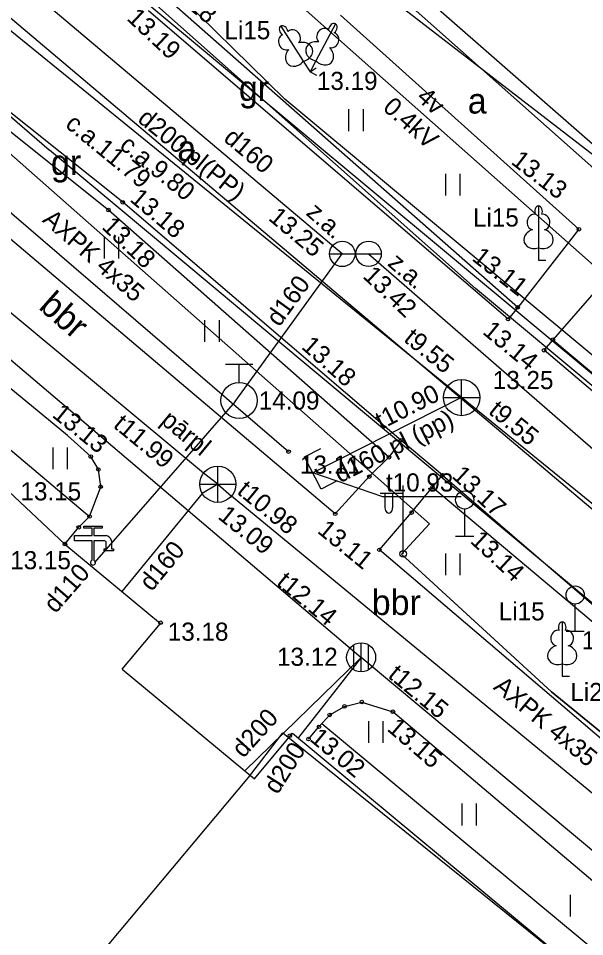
# Model space of a CAD drawing. Extents: x 503877 to 504025, y 304562 to 304725.
# Drawn here: x 503933 to 503948.61, y 304593.32 to 304618.66 of the extents above; entities that cross this region are included whole.
import ezdxf

# ---------------------------------------------------------------- set-up
doc = ezdxf.new("R2010")
doc.units = 0
for name, color, linetype in [('24', 7, 'Continuous'), ('25', 7, 'Continuous'), ('42', 7, 'Continuous'), ('APGS_ACRL_####_####_#', 7, 'Continuous'), ('APGS_ELEM_####_####_#', 7, 'Continuous'), ('APGS_VADP_ZSPR_####_#', 7, 'Continuous'), ('APGS_VADP_ZSPR_TKST_#', 7, 'Continuous'), ('BUVE_BDET_####_####_#', 7, 'Continuous'), ('BUVE_EKAS_####_####_#', 7, 'Continuous'), ('CELI_CMAL_####_####_#', 7, 'Continuous'), ('CELI_CSEG_####_TKST_#', 7, 'Continuous'), ('CELI_ELEM_####_####_#', 7, 'Continuous'), ('CELI_TAKA_####_####_#', 7, 'Continuous'), ('ELEK_VADV_ZSPR_####_#', 7, 'Continuous'), ('ELEK_VADV_ZSPR_TKST_#', 7, 'Continuous'), ('GAZE_VADP_VSP2_####_#', 7, 'Continuous'), ('Level 46', 7, 'Continuous'), ('LKAN_ELEM_####_####_#', 7, 'Continuous'), ('LKAN_ELEM_PAST_TKST_#', 7, 'Continuous'), ('LKAN_VADP_PAST_####_#', 7, 'Continuous'), ('LKAN_VADP_PAST_TKST_#', 7, 'Continuous'), ('RELJ_AATZ_####_TKST_#', 7, 'Continuous'), ('RELJ_ELEM_####_####_#', 7, 'Continuous'), ('SAKK_KKAN_####_####_#', 7, 'Continuous'), ('SAKT_VADP_KABE_####_#', 7, 'Continuous'), ('SAKT_VADP_NEDR_####_#', 7, 'Continuous'), ('SKAN_ELEM_####_####_#', 7, 'Continuous'), ('SKAN_ELEM_PAST_TKST_#', 7, 'Continuous'), ('SKAN_VADP_PAST_####_#', 7, 'Continuous'), ('SKAN_VADP_PAST_####_I', 7, 'Continuous'), ('SKAN_VADP_PAST_TKST_#', 7, 'Continuous'), ('SKAN_VADP_PAST_TKST_I', 7, 'Continuous'), ('SKAN_VADP_SPDK_TKST_I', 7, 'Continuous'), ('TERT_DIAM_####_TKST_#', 7, 'Continuous'), ('TERT_ELEM_####_####_#', 7, 'Continuous'), ('TERT_KRND_####_####_#', 7, 'Continuous'), ('UDTK_ELEM_####_####_#', 7, 'Continuous'), ('UDTK_ELEM_####_TKST_#', 7, 'Continuous'), ('UDTK_VADP_UDEN_####_#', 7, 'Continuous'), ('UDTK_VADP_UDEN_####_I', 7, 'Continuous'), ('UDTK_VADP_UDEN_TKST_#', 7, 'Continuous')]:
    doc.layers.add(name, color=color, linetype=linetype)

msp = doc.modelspace()

# ---------------------------------------------------------------- linework, layer by layer
at = {"layer": '24'}
msp.add_line((503960.823, 304605.633), (503933.144, 304627.024), dxfattribs=at)
at = {"layer": '25'}
msp.add_line((503924.947, 304625.297), (503985.325, 304574.255), dxfattribs=at)
at = {"layer": '42'}
msp.add_lwpolyline([(503940.294, 304598.947), (503951.661, 304589.773), (503949.864, 304587.645), (503954.733, 304583.621), (503953.927, 304582.557), (503960.49, 304577.208), (503958.987, 304575.41), (503959.865, 304574.697), (503955.838, 304569.828), (503955.063, 304570.502), (503953.67, 304568.891), (503946.74, 304574.542), (503947.217, 304575.092), (503942.561, 304578.835), (503942.084, 304578.358), (503930.754, 304587.457), (503939.344, 304597.708)], close=True, dxfattribs=at)
at = {"layer": 'APGS_ACRL_####_####_#'}
for p, q in [((503947.7, 304600.079), (503944.899, 304602.648)), ((503955.54, 304593.612), (503947.7, 304600.079))]:
    msp.add_line(p, q, dxfattribs=at)
at = {"layer": 'APGS_ELEM_####_####_#'}
for p, q in [((503943.611, 304603.885), (503943.611, 304605.768)), ((503943.611, 304605.552), (503942.976, 304605.547)), ((503943.111, 304605.548), (503943.111, 304605.156)), ((503943.321, 304605.55), (503943.321, 304605.156))]:
    msp.add_line(p, q, dxfattribs=at)
msp.add_circle((503943.611, 304603.885), 0.09, dxfattribs=at)
msp.add_ellipse((503943.216, 304605.156), major_axis=(0, 0.151), ratio=0.695971, start_param=1.570796, end_param=4.712389, dxfattribs=at)
at = {"layer": 'APGS_VADP_ZSPR_####_#'}
for p, q in [((503930.322, 304617.086), (503944.336, 304604.708)), ((503944.336, 304604.708), (503943.564, 304603.872)), ((503943.564, 304603.872), (503947.7, 304600.079)), ((503947.7, 304600.079), (503955.752, 304593.437))]:
    msp.add_line(p, q, dxfattribs=at)
at = {"layer": 'BUVE_BDET_####_####_#'}
msp.add_line((503941.373, 304599.205), (503951.794, 304590.537), dxfattribs=at)
at = {"layer": 'BUVE_EKAS_####_####_#'}
for p, q in [((503927.634, 304610.394), (503934.287, 304604.153)), ((503934.287, 304604.153), (503936.919, 304601.964)), ((503935.866, 304600.697), (503936.919, 304601.964)), ((503935.866, 304600.697), (503939.51, 304597.678)), ((503939.51, 304597.678), (503940.557, 304598.938)), ((503940.557, 304598.938), (503951.781, 304589.603))]:
    msp.add_line(p, q, dxfattribs=at)
at = {"layer": 'CELI_CMAL_####_####_#'}
for p, q in [((503950.55, 304613.018), (503942.522, 304620.157)), ((503946.502, 304610.359), (503936.593, 304618.863)), ((503941.882, 304618.748), (503948.456, 304612.839)), ((503935.883, 304613.584), (503931.107, 304617.397)), ((503941.74, 304604.987), (503929.195, 304615.6)), ((503943.556, 304607.012), (503935.883, 304613.584)), ((503947.498, 304609.501), (503950.55, 304613.018)), ((503948.456, 304612.839), (503946.769, 304610.685)), ((503927.574, 304611.135), (503934.968, 304604.913)), ((503934.355, 304607.151), (503929.569, 304611.095)), ((503946.769, 304610.685), (503946.502, 304610.359)), ((503962.594, 304596.657), (503947.498, 304609.501)), ((503935, 304606.567), (503934.355, 304607.151)), ((503943.556, 304607.012), (503943.218, 304606.546)), ((503944.692, 304606.054), (503943.556, 304607.012)), ((503935.209, 304606.21), (503935, 304606.567)), ((503943.218, 304606.546), (503942.679, 304606.013)), ((503935.274, 304605.736), (503935.209, 304606.21)), ((503942.679, 304606.013), (503941.74, 304604.987)), ((503944.42, 304605.72), (503944.692, 304606.054)), ((503944.692, 304606.054), (503957.877, 304594.69)), ((503934.968, 304604.913), (503935.274, 304605.736)), ((503943.846, 304605.021), (503944.42, 304605.72)), ((503934.67, 304604.614), (503934.968, 304604.913)), ((503942.956, 304603.993), (503943.846, 304605.021)), ((503934.287, 304604.153), (503934.67, 304604.614)), ((503956.326, 304592.583), (503942.956, 304603.993)), ((503941.995, 304599.672), (503942.472, 304599.793)), ((503942.472, 304599.793), (503943.33, 304599.524)), ((503941.587, 304599.439), (503941.995, 304599.672)), ((503954.372, 304590.15), (503943.33, 304599.524)), ((503941.291, 304599.109), (503941.587, 304599.439)), ((503941.005, 304598.769), (503941.291, 304599.109))]:
    msp.add_line(p, q, dxfattribs=at)
at = {"layer": 'CELI_ELEM_####_####_#'}
for p, q in [((503945.309, 304604.369), (503945.309, 304605.119)), ((503945.059, 304604.369), (503945.559, 304604.369)), ((503948.353, 304601.746), (503948.353, 304602.496)), ((503948.103, 304601.746), (503948.603, 304601.746))]:
    msp.add_line(p, q, dxfattribs=at)
for centre in [(503945.309, 304605.369), (503948.353, 304602.746)]:
    msp.add_circle(centre, 0.25, dxfattribs=at)
at = {"layer": 'CELI_TAKA_####_####_#'}
for p, q in [((503946.769, 304610.685), (503936.798, 304619.482)), ((503935.489, 304613.368), (503931.027, 304616.929)), ((503943.218, 304606.546), (503935.489, 304613.368)), ((503947.74, 304609.79), (503962.913, 304596.977)), ((503944.42, 304605.72), (503957.828, 304594.446))]:
    msp.add_line(p, q, dxfattribs=at)
at = {"layer": 'ELEK_VADV_ZSPR_####_#'}
msp.add_line((503938.2, 304621.309), (503972.501, 304590.85), dxfattribs=at)
at = {"layer": 'GAZE_VADP_VSP2_####_#'}
for p, q in [((503928.77, 304619.428), (503933.852, 304615.028)), ((503933.862, 304615.034), (503938.375, 304611.261)), ((503938.375, 304611.261), (503939.829, 304610.045)), ((503939.829, 304610.045), (503957.313, 304595.425))]:
    msp.add_line(p, q, dxfattribs=at)
at = {"layer": 'Level 46'}
msp.add_line((503943.333, 304620.019), (504006.701, 304564.361), dxfattribs=at)
at = {"layer": 'LKAN_ELEM_####_####_#'}
for p, q in [((503942.253, 304600.68), (503942.253, 304601.372)), ((503942.453, 304600.626), (503942.453, 304601.426)), ((503942.653, 304600.68), (503942.653, 304601.372))]:
    msp.add_line(p, q, dxfattribs=at)
msp.add_circle((503942.453, 304601.026), 0.4, dxfattribs=at)
at = {"layer": 'LKAN_VADP_PAST_####_#'}
for p, q in [((503924.482, 304616.293), (503942.453, 304601.026)), ((503939.243, 304597.899), (503942.453, 304601.026)), ((503942.453, 304601.026), (503940.729, 304598.812)), ((503953.386, 304591.874), (503942.453, 304601.026))]:
    msp.add_line(p, q, dxfattribs=at)
at = {"layer": 'RELJ_ELEM_####_####_#'}
for centre in [(503935.883, 304613.584), (503935.489, 304613.368), (503948.456, 304612.839), (503946.769, 304610.685), (503946.502, 304610.359), (503947.74, 304609.79), (503947.498, 304609.501), (503943.556, 304607.012), (503935, 304606.567), (503940.453, 304606.703), (503943.218, 304606.546), (503935.209, 304606.21), (503942.679, 304606.013), (503944.692, 304606.054), (503935.274, 304605.736), (503944.42, 304605.72), (503934.968, 304604.913), (503941.74, 304604.987), (503943.846, 304605.021), (503934.67, 304604.614), (503934.287, 304604.153), (503942.956, 304603.993), (503936.927, 304601.982), (503942.472, 304599.793), (503941.995, 304599.672), (503943.33, 304599.524), (503941.587, 304599.439), (503941.291, 304599.109), (503940.487, 304598.862), (503941.005, 304598.769)]:
    msp.add_circle(centre, 0.05, dxfattribs=at)
at = {"layer": 'SAKK_KKAN_####_####_#'}
for p, q in [((503945.607, 304611.208), (503936.176, 304619.589)), ((503968.613, 304591.954), (503945.607, 304611.208))]:
    msp.add_line(p, q, dxfattribs=at)
at = {"layer": 'SAKT_VADP_KABE_####_#'}
for p, q in [((503940.354, 304616.433), (503936.38, 304620.327)), ((503971.653, 304590.306), (503940.354, 304616.433))]:
    msp.add_line(p, q, dxfattribs=at)
at = {"layer": 'SAKT_VADP_NEDR_####_#'}
msp.add_line((503997.217, 304568.475), (503924.507, 304629.123), dxfattribs=at)
at = {"layer": 'SKAN_ELEM_####_####_#'}
for p, q in [((503945.224, 304607.695), (503945.224, 304608.695)), ((503944.724, 304608.195), (503945.724, 304608.195)), ((503938.502, 304605.302), (503938.502, 304606.302)), ((503938.002, 304605.802), (503939.002, 304605.802))]:
    msp.add_line(p, q, dxfattribs=at)
msp.add_lwpolyline([(503941.794, 304605.895), (503941.348, 304605.669), (503940.896, 304606.561), (503941.342, 304606.787)], dxfattribs=at)
for centre in [(503945.224, 304608.195), (503938.502, 304605.802)]:
    msp.add_circle(centre, 0.5, dxfattribs=at)
at = {"layer": 'SKAN_VADP_PAST_####_#'}
for p, q in [((503938.11, 304606.113), (503924.52, 304617.411)), ((503938.502, 304605.802), (503938.11, 304606.113)), ((503938.502, 304605.802), (503938.072, 304605.546)), ((503938.502, 304605.802), (503938.881, 304605.476)), ((503938.072, 304605.546), (503935.86, 304602.845)), ((503971.339, 304578.696), (503938.881, 304605.476))]:
    msp.add_line(p, q, dxfattribs=at)
at = {"layer": 'SKAN_VADP_PAST_####_I'}
for p, q in [((503945.224, 304608.195), (503926.692, 304623.27)), ((503945.224, 304608.195), (503941.122, 304606.115)), ((503973.287, 304585.319), (503945.224, 304608.195))]:
    msp.add_line(p, q, dxfattribs=at)
at = {"layer": 'SKAN_VADP_PAST_TKST_I'}
msp.add_lwpolyline([(503945.214, 304605.453), (503943.055, 304605.453), (503941.122, 304606.115)], dxfattribs=at)
at = {"layer": 'TERT_ELEM_####_####_#'}
for p, q in [((503940.859, 304617.476), (503941.047, 304617.184)), ((503941.208, 304617.491), (503941.047, 304617.184)), ((503941.047, 304617.184), (503941.215, 304617.292)), ((503941.047, 304617.184), (503941.224, 304617.091)), ((503942.117, 304615.551), (503942.117, 304616.151)), ((503942.517, 304615.551), (503942.517, 304616.151)), ((503944.786, 304613.77), (503944.786, 304614.37)), ((503945.186, 304613.77), (503945.186, 304614.37)), ((503935.374, 304612.034), (503935.374, 304612.634)), ((503935.774, 304612.034), (503935.774, 304612.634)), ((503947.343, 304612.331), (503947.343, 304611.984)), ((503947.343, 304611.984), (503947.543, 304611.984)), ((503938.148, 304609.73), (503938.148, 304610.33)), ((503938.548, 304609.73), (503938.548, 304610.33)), ((503933.962, 304606.221), (503933.962, 304606.821)), ((503934.362, 304606.221), (503934.362, 304606.821)), ((503944.786, 304603.296), (503944.786, 304603.896)), ((503945.186, 304603.296), (503945.186, 304603.896)), ((503947.997, 304600.851), (503947.997, 304600.504)), ((503947.997, 304600.504), (503948.197, 304600.504)), ((503942.663, 304598.664), (503942.663, 304599.264)), ((503943.063, 304598.664), (503943.063, 304599.264)), ((503945.234, 304596.39), (503945.234, 304596.99)), ((503945.634, 304596.39), (503945.634, 304596.99)), ((503948.225, 304593.876), (503948.225, 304594.476))]:
    msp.add_line(p, q, dxfattribs=at)
for points in [[(503940.235, 304618.445), (503940.859, 304617.476)], [(503940.436, 304618.298), (503940.435, 304618.299)], [(503941.745, 304618.512), (503941.208, 304617.491)], [(503941.716, 304618.264), (503941.715, 304618.266)], [(503947.343, 304613.484), (503947.343, 304612.331)], [(503947.433, 304613.252), (503947.432, 304613.253)], [(503947.997, 304602.004), (503947.997, 304600.851)], [(503948.087, 304601.772), (503948.086, 304601.773)]]:
    msp.add_lwpolyline(points, dxfattribs=at)
for centre, major_axis, ratio, start_param, end_param in [((503941.675, 304618.379), (-0.07, -0.133), 0.707107, 3.14537, 5.287485), ((503940.317, 304618.319), (0.081, -0.126), 0.707107, 3.14537, 5.287485), ((503940.316, 304618.319), (0.081, -0.126), 0.707107, 0.995701, 3.137816), ((503940.584, 304618.141), (0.148, -0.158), 0.861323, 0, 3.141593), ((503941.424, 304618.178), (-0.133, -0.17), 0.861323, 3.141593, 6.283185), ((503941.675, 304618.379), (-0.07, -0.133), 0.707107, 0.995701, 3.137816), ((503940.368, 304618.002), (0.082, -0.2), 0.861323, 3.141593, 6.283185), ((503941.243, 304617.751), (0.316, -0.059), 0.814445, 1.570796, 4.752015), ((503941.651, 304618.058), (-0.065, -0.206), 0.861323, 0, 3.141593), ((503940.651, 304617.634), (0.206, 0.246), 0.814445, 1.570796, 4.752015), ((503940.801, 304617.731), (-0.309, -0.086), 0.814445, 1.531171, 4.712389), ((503941.402, 304617.667), (-0.227, 0.227), 0.814445, 1.531171, 4.712389), ((503947.343, 304613.334), (0, -0.15), 0.707107, 3.14537, 5.287485), ((503947.343, 304613.334), (0, -0.15), 0.707107, 0.995701, 3.137816), ((503947.215, 304613.039), (-0.039, -0.212), 0.861323, 3.141593, 6.283185), ((503947.471, 304613.039), (0.039, -0.212), 0.861323, 0, 3.141593), ((503947.253, 304612.577), (0.307, 0.095), 0.814445, 1.570796, 4.752015), ((503947.433, 304612.577), (-0.307, 0.095), 0.814445, 1.531171, 4.712389), ((503947.997, 304601.854), (0, -0.15), 0.707107, 3.14537, 5.287485), ((503947.997, 304601.854), (0, -0.15), 0.707107, 0.995701, 3.137816), ((503947.869, 304601.559), (-0.039, -0.212), 0.861323, 3.141593, 6.283185), ((503948.125, 304601.559), (0.039, -0.212), 0.861323, 0, 3.141593), ((503947.907, 304601.097), (0.307, 0.095), 0.814445, 1.570796, 4.752015), ((503948.087, 304601.097), (-0.307, 0.095), 0.814445, 1.531171, 4.712389)]:
    msp.add_ellipse(centre, major_axis=major_axis, ratio=ratio, start_param=start_param, end_param=end_param, dxfattribs=at)
at = {"layer": 'TERT_KRND_####_####_#'}
msp.add_line((503929.802, 304615.876), (503940.453, 304606.703), dxfattribs=at)
at = {"layer": 'UDTK_ELEM_####_####_#'}
for p, q in [((503941.582, 304612.16), (503942.284, 304612.16)), ((503942.307, 304612.162), (503943.009, 304612.162)), ((503938.714, 304609.114), (503939.464, 304609.114)), ((503939.089, 304608.614), (503939.089, 304609.114)), ((503934.811, 304604.592), (503934.811, 304604.642)), ((503934.811, 304604.642), (503935.311, 304604.642)), ((503935.036, 304604.592), (503934.811, 304604.592)), ((503935.036, 304604.392), (503935.036, 304604.592)), ((503935.311, 304604.592), (503935.086, 304604.592)), ((503935.086, 304604.592), (503935.086, 304604.392)), ((503935.311, 304604.642), (503935.311, 304604.592)), ((503934.55, 304604.392), (503935.036, 304604.392)), ((503934.55, 304604.242), (503934.55, 304604.392)), ((503935.086, 304604.392), (503935.422, 304604.392)), ((503935.036, 304604.242), (503934.55, 304604.242)), ((503935.036, 304603.706), (503935.036, 304604.242)), ((503935.392, 304604.242), (503935.086, 304604.242)), ((503935.086, 304604.242), (503935.086, 304603.706)), ((503935.422, 304604.018), (503935.422, 304604.213)), ((503935.572, 304604.242), (503935.572, 304604.018)), ((503935.372, 304603.968), (503935.372, 304604.018)), ((503935.372, 304604.018), (503935.422, 304604.018)), ((503935.622, 304603.968), (503935.372, 304603.968)), ((503935.572, 304604.018), (503935.622, 304604.018)), ((503935.622, 304604.018), (503935.622, 304603.968))]:
    msp.add_line(p, q, dxfattribs=at)
for centre, radius in [((503941.933, 304612.16), 0.351), ((503942.658, 304612.162), 0.351), ((503939.089, 304608.114), 0.5)]:
    msp.add_circle(centre, radius, dxfattribs=at)
for centre, radius, start, end in [((503935.353, 304604.174), 0.229, 17.4344, 72.5656), ((503935.353, 304604.174), 0.0792, 29.8818, 60.1182), ((503935.061, 304603.642), 0.069, 111.235, 68.765)]:
    msp.add_arc(centre, radius, start, end, dxfattribs=at)
at = {"layer": 'UDTK_VADP_UDEN_####_#'}
for p, q in [((503941.933, 304612.16), (503932.733, 304619.928)), ((503938.985, 304608.09), (503941.933, 304612.16)), ((503938.985, 304608.09), (503935.103, 304603.648))]:
    msp.add_line(p, q, dxfattribs=at)
at = {"layer": 'UDTK_VADP_UDEN_####_I'}
for p, q in [((503941.933, 304612.16), (503942.658, 304612.162)), ((503942.658, 304612.162), (503968.511, 304589.634))]:
    msp.add_line(p, q, dxfattribs=at)

# ---------------------------------------------------------------- texts
at = {"layer": 'APGS_VADP_ZSPR_TKST_#'}
for rotation, p in [(318.5463, (503933.64, 304613.062)), (320.1197, (503946.074, 304600.168))]:
    msp.add_text('AXPK 4x35', height=0.5, rotation=rotation, dxfattribs=at).set_placement(p)
at = {"layer": 'CELI_CSEG_####_TKST_#'}
for s, p in [('gr', (503939.083, 304616.379)), ('a', (503945.392, 304616.033)), ('a', (503937.386, 304614.724)), ('gr', (503933.903, 304614.336)), ('bbr', (503942.746, 304602.195))]:
    msp.add_text(s, height=0.7, dxfattribs=at).set_placement(p)
msp.add_text('bbr', height=0.7, rotation=318.6552, dxfattribs=at).set_placement((503933.534, 304610.663))
at = {"layer": 'ELEK_VADV_ZSPR_TKST_#'}
for s, p in [('4v', (503943.951, 304616.436)), ('0.4kV', (503943.022, 304616.157))]:
    msp.add_text(s, height=0.5, rotation=318.3949, dxfattribs=at).set_placement(p)
at = {"layer": 'LKAN_ELEM_PAST_TKST_#'}
msp.add_text(' 13.12', height=0.5, dxfattribs=at).set_placement((503939.948, 304600.792))
at = {"layer": 'LKAN_VADP_PAST_TKST_#'}
for s, rotation, p in [('t12.14', 320.3604, (503940.093, 304603.049)), ('t12.15', 320.2454, (503943.165, 304600.491)), ('d200', 47.8765, (503939.206, 304598.225)), ('d200', 57.7939, (503940.151, 304597.22))]:
    msp.add_text(s, height=0.5, rotation=rotation, dxfattribs=at).set_placement(p)
at = {"layer": 'RELJ_AATZ_####_TKST_#'}
for s, rotation, p in [(' 13.18', 320.1951, (503936.79, 304619.675)), (' 13.19', 316.8008, (503935.832, 304618.76)), (' 13.13', 322.3247, (503946.412, 304614.777)), (' 13.18', 319.757, (503935.908, 304613.755)), (' 13.18', 316.3488, (503935.144, 304613.006)), (' 13.11', 321.8595, (503945.335, 304612.114)), (' 13.14', 320.529, (503945.629, 304610.093)), (' 13.18', 318.5574, (503940.641, 304609.691)), (' 13.13', 321.0124, (503933.765, 304607.796)), (' 13.17', 317.1938, (503944.794, 304606.128)), (' 13.11', 320.7363, (503941.076, 304604.6)), (' 13.14', 317.3651, (503945.297, 304604.334)), (' 13.15', 319.1708, (503943.003, 304599.146)), (' 13.02', 320.3259, (503940.867, 304598.86))]:
    msp.add_text(s, height=0.5, rotation=rotation, dxfattribs=at).set_placement(p)
for s, p in [(' 13.19', (503941.047, 304616.684)), (' 13.11', (503940.581, 304606.095)), (' 13.15', (503932.876, 304605.358)), (' 13.18', (503936.937, 304601.485)), (' 13.15', (503948.353, 304601.246))]:
    msp.add_text(s, height=0.5, dxfattribs=at).set_placement(p)
at = {"layer": 'SKAN_ELEM_PAST_TKST_#'}
msp.add_text(' 13.25', height=0.5, dxfattribs=at).set_placement((503945.896, 304608.428))
for s, rotation, p in [('pārpl', 320.2846, (503936.9, 304607.506)), (' 13.09', 321.3105, (503938.332, 304604.992))]:
    msp.add_text(s, height=0.5, rotation=rotation, dxfattribs=at).set_placement(p)
at = {"layer": 'SKAN_VADP_PAST_TKST_#'}
for s, rotation, p in [('t11.99', 320.2635, (503935.591, 304607.394)), ('t10.98', 320.4757, (503939.003, 304605.567)), ('d160', 50.6737, (503936.678, 304602.824))]:
    msp.add_text(s, height=0.5, rotation=rotation, dxfattribs=at).set_placement(p)
at = {"layer": 'SKAN_VADP_PAST_TKST_I'}
for s, rotation, p in [('d200 pl(PP)', 320.8731, (503936.261, 304615.83)), ('c.a.9.80', 320.8731, (503935.764, 304615.095)), ('t9.55', 320.8731, (503943.6, 304609.767)), ('t10.90', 26.8882, (503943.003, 304607.3)), ('t9.55', 320.8731, (503945.936, 304607.773)), ('d160 pl (pp)', 26.8882, (503941.873, 304605.827))]:
    msp.add_text(s, height=0.5, rotation=rotation, dxfattribs=at).set_placement(p)
msp.add_text('t10.93', height=0.5, dxfattribs=at).set_placement((503943.137, 304605.603))
at = {"layer": 'SKAN_VADP_SPDK_TKST_I'}
msp.add_text('c.a.11.79', height=0.5, rotation=320.6077, dxfattribs=at).set_placement((503934.267, 304615.683))
at = {"layer": 'TERT_DIAM_####_TKST_#'}
for s, p in [('Li15', (503938.685, 304618.082)), ('Li15', (503945.536, 304612.914)), ('Li15', (503946.246, 304602.047)), ('Li20', (503948.22, 304599.82))]:
    msp.add_text(s, height=0.5, dxfattribs=at).set_placement(p)
at = {"layer": 'UDTK_ELEM_####_TKST_#'}
for s, rotation, p in [('z.a.', 318.0284, (503940.909, 304613.259)), (' 13.25', 319.9991, (503939.728, 304613.235)), ('z.a.', 319.0555, (503943.156, 304611.86)), (' 13.42', 316.4235, (503942.339, 304611.647))]:
    msp.add_text(s, height=0.5, rotation=rotation, dxfattribs=at).set_placement(p)
for s, p in [(' 14.09', (503939.445, 304607.863)), (' 13.15', (503932.593, 304603.458))]:
    msp.add_text(s, height=0.5, dxfattribs=at).set_placement(p)
at = {"layer": 'UDTK_VADP_UDEN_TKST_#'}
for s, rotation, p in [('d160', 319.824, (503938.632, 304615.302)), ('d160', 54.0833, (503940.199, 304610.125)), ('d110', 48.846, (503934.028, 304602.217))]:
    msp.add_text(s, height=0.5, rotation=rotation, dxfattribs=at).set_placement(p)

doc.saveas('drawing.dxf')
